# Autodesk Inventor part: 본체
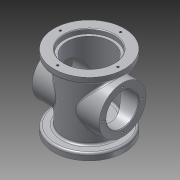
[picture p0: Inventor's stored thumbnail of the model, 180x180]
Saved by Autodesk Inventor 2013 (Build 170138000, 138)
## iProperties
Created: 2018-02
Part Number: 본체
Material: 알루미늄 6061
Document SubType Name: Modeling
Designer: Administrator
Density: 2.71 g/cm^3
Mass: 759.257 g
Surface Area: 822.557 cm^2
Volume: 280.169 cm^3
Author: Administrator
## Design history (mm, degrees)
sketch "스케치1"
  geometry: C1 r 38 at (0, 0); 1 further point
  constraints: 1 centre point, 1 coincident
  dimensions: "d0" = 76 diameter of C1
extrude "돌출1" new body sketch "스케치1" stored distance "d1" = 108; taper "d2" = 0 deg
sketch "스케치2"
  geometry: C1 r 38 at (0, 0) reference; C2 r 52.5 at (0, 0)
  constraints: 1 centre point, 1 coincident
  dimensions: "d3" = 105 diameter of C2
extrude "돌출2" join sketch "스케치2" distance "d4" = 10; taper "d5" = 0 deg
sketch "스케치3"
  geometry: C1 r 52.5 at (0, 0) reference; C2 r 33 at (0, 0)
  constraints: 1 centre point, 1 coincident
  dimensions: "d6" = 66 diameter of C2
extrude "돌출3" cut sketch "스케치3" distance "d7" = 86; taper "d8" = 0 deg
sketch "스케치4"
  geometry: C1 r 33 at (0, 0) reference; C2 r 52.5 at (0, 0) reference; C3 r 37 at (0, 0)
  constraints: 1 centre point, 1 coincident
  dimensions: "d9" = 74 diameter of C3
extrude "돌출4" cut sketch "스케치4" distance "d10" = 7; taper "d11" = 0 deg
chamfer "모따기1" distance "d12" = 1; stored, may be unused: second distance "d13" = 2, angle "d14" = 45 deg
sketch "스케치5"
  geometry: C1 r 52.5 at (0, 0) reference; C2 r 34 at (0, 0)
  constraints: 1 centre point, 1 coincident
  dimensions: "d15" = 68 diameter of C2
extrude "돌출5" cut sketch "스케치5" distance "d17" = 16; taper "d18" = 0 deg
sketch "스케치6"
  geometry: C1 r 34 at (0, 0) reference; C2 r 5 at (0, 0)
  constraints: 1 centre point, 1 coincident
  dimensions: "d19" = 10 diameter of C2
extrude "돌출6" cut sketch "스케치6" distance "d20" = 36.5; taper "d21" = 0 deg
node "작업 평면2"
sketch "스케치7"
  geometry: C1 r 35 at (0, 0); 1 further point
  constraints: 1 centre point, 1 coincident
  dimensions: "d23" = 70 diameter of C1
extrude "돌출7" join sketch "스케치7" stored distance "d24" = 36.5; taper "d25" = 0 deg
sketch "스케치8"
  geometry: C1 r 35 at (0, 0) reference; C2 r 24 at (0, 0)
  constraints: 1 centre point, 1 coincident
  dimensions: "d26" = 48 diameter of C2
extrude "돌출8" cut sketch "스케치8" distance "d27" = 133.75; taper "d28" = 0 deg
sketch "스케치9" dims "d29" = 58
  geometry: C1 r 24 at (0, 0) reference; 2 further points
  constraints: 1 coincident, 1 horizontal alignment, 2 other
hole "구멍1" sketch "스케치9" at (-29, 0) diameter "d30" = 3.242; stored, may be unused: countersink angle "d34" = 90 deg, drill point angle "d36" = 118 deg; dims "d31" = 4, "d32" = 4, "d33" = 2, "d35" = 6
sketch "스케치10" dims "d40" = 90
  geometry: C1 r 52.5 at (0, 0) reference; 2 further points
  constraints: 1 coincident, 3 other
hole "구멍2" sketch "스케치10" at (1.966, 44.957) diameter "d41" = 3.242; stored, may be unused: countersink angle "d45" = 90 deg, drill point angle "d47" = 118 deg; dims "d42" = 4, "d43" = 4, "d44" = 2, "d46" = 6
chamfer "모따기2" distance "d51" = 1; stored, may be unused: second distance "d52" = 2, angle "d53" = 45 deg
fillet "모깎기3" dims "d80" = 3
fillet "모깎기4" dims "d81" = 3
fillet "모깎기5" dims "d82" = 3
node "작업 평면6"
sketch "스케치23"
  geometry: L1 (-7, 13)-(7, 13); L2 (7, 13)-(7, -13); L3 (7, -13)-(-7, -13); L4 (-7, -13)-(-7, 13); C1 r 7 at (0, 13); 4 further points
  constraints: 8 end point, 4 midpoint, 2 horizontal alignment, 2 parallel, 2 tangent, 1 centre point, 1 horizontal, 1 perpendicular, 1 vertical, 1 vertical alignment, 2 other
  dimensions: "d102" = 14 diameter of C1; "d105" = 13 distance of point (0, -13) point (0, 0)
node "작업 평면7"
node "작업 평면9"
sketch "스케치38"
  geometry: 1 further point
sketch "스케치39"
  geometry: 1 further point
extrude "돌출19" join sketch "스케치23" stored distance "d150" = 14; taper "d151" = 0 deg
sketch "스케치40"
  geometry: A1 r 7 centre (0, -13) between (-7, -13) and (7, -13) reference; A2 r 7 centre (0, 13) between (7, 13) and (-7, 13) reference; 3 further points
  constraints: 2 coincident
hole "구멍6" sketch "스케치40" at (0, 13), (0, -13) diameter "d152" = 4.134; stored, may be unused: countersink angle "d156" = 90 deg, drill point angle "d158" = 118 deg; dims "d153" = 6, "d154" = 4, "d155" = 2, "d157" = 8
node "솔리드1"
mirror "대칭1"
mirror "대칭2"
pattern_circular "원형 패턴1" dims angle "d38" = 360 deg
mirror "대칭3"
pattern_circular "원형 패턴2" dims angle "d49" = 360 deg
other parameters: "d101" = 55
